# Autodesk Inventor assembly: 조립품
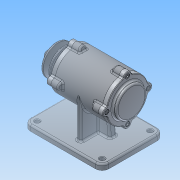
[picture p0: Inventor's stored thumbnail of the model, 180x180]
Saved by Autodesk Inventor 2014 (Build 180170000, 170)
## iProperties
Created: 2015-12
Part Number: 조립품
Document SubType Name: Assembly
Designer: nert
Author: nert
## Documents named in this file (11)
- C:\Users\nert\Desktop\451207V1010\조립품.iam
- C:\Users\nert\Desktop\451207V1010\본체.ipt
- C:\Users\nert\Desktop\451207V1010\커버.ipt
- C:\Users\nert\Desktop\451207V1010\커버2.ipt
- C:\Users\nert\Desktop\451207V1010\베어링 6204.ipt
- C:\Users\nert\Desktop\451207V1010\축.ipt
- C:\Users\nert\Desktop\451207V1010\오일실.ipt
- C:\Users\nert\Desktop\451207V1010\V-벨트풀리.ipt
- C:\Users\nert\Desktop\451207V1010\키(4 x 4 x 12).ipt
- C:\Users\nert\Desktop\451207V1010\너트 M12x1.25.ipt
- C:\Users\nert\Desktop\451207V1010\볼트 M4 x 12.ipt
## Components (6 placed, 5 different names)
1. KS B 2023 6204 - 20 x 47 x 14:1
2. KS B 2023 6204 - 20 x 47 x 14:2
3. KS B 2804 D D - 20 32 8:1
4. V-벨트풀리:1
5. KS B 1311 (I) 4 x 4 x 12:1
6. KS B 1012 클래스 1 일반 - 미터 M12x1.25:1
